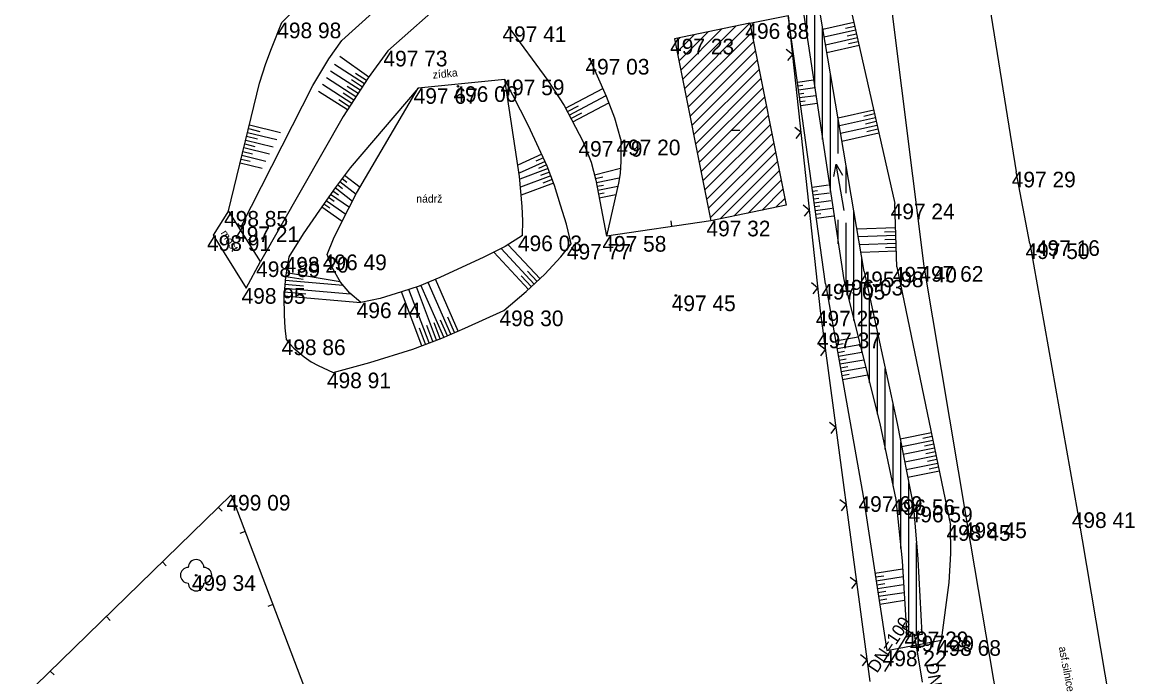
# Model space of a CAD drawing. Extents: x -554123 to -553118, y -1076825 to -1073672.
# Drawn here: x -553501.5 to -553430.4, y -1076768 to -1076726.2 of the extents above; entities that cross this region are included whole.
import ezdxf

# ---------------------------------------------------------------- set-up
doc = ezdxf.new("R2010")
doc.units = 0
for name, color, linetype in [('1', 7, 'Continuous'), ('12', 7, 'Continuous'), ('14', 7, 'Continuous'), ('17', 7, 'Continuous'), ('18', 7, 'Continuous'), ('26', 7, 'Continuous'), ('27', 7, 'Continuous'), ('28', 7, 'Continuous'), ('32', 7, 'Continuous'), ('34', 7, 'Continuous'), ('40', 7, 'Continuous'), ('47', 7, 'Continuous'), ('49', 7, 'Continuous'), ('52', 7, 'Continuous'), ('6', 7, 'Continuous')]:
    doc.layers.add(name, color=color, linetype=linetype)

# ---------------------------------------------------------------- blocks, each defined once
blk = doc.blocks.new('POINT_DISPLAY')
blk.add_line((0, 0), (0, 0))
blk = doc.blocks.new('T')
at = {"layer": '6'}
blk.add_circle((0, 0), 0.05, dxfattribs=at)
blk = doc.blocks.new('VOTOK')
at = {"layer": '28'}
for p, q in [((-3.001, 0), (0, 0)), ((-0.75, 0.282), (0, 0)), ((0, 0), (-0.75, -0.28))]:
    blk.add_line(p, q, dxfattribs=at)
blk = doc.blocks.new('JS800')
at = {"layer": '49'}
blk.add_text('DN=800', height=0.8, rotation=359.99988, dxfattribs=at).set_placement((0, 0))
blk = doc.blocks.new('STL')
at = {"layer": '34'}
blk.add_circle((0, 0), 0.05, dxfattribs=at)
for centre, start, end in [((0, 0.5), 0, 180), ((-0.5, 0), 90, 270), ((0.5, 0), 270, 90), ((0, -0.5), 180, 0)]:
    blk.add_arc(centre, 0.5, start, end, dxfattribs=at)
blk = doc.blocks.new('VYUST')
at = {"layer": '40'}
for p, q in [((-0.35, 0.501), (0, 0.5)), ((0, 0.5), (0, -0.5)), ((0, 0), (3, 0)), ((-0.35, -0.5), (0, -0.5))]:
    blk.add_line(p, q, dxfattribs=at)
blk = doc.blocks.new('BN')
at = {"layer": '47'}
blk.add_line((-0.25, 0), (0.25, 0), dxfattribs=at)
blk = doc.blocks.new('JS100')
at = {"layer": '49'}
blk.add_text('DN=100', height=0.8, rotation=359.99998, dxfattribs=at).set_placement((0, 0))

msp = doc.modelspace()

# ---------------------------------------------------------------- linework, layer by layer
at = {"layer": '12'}
for p, q in [((-553455.03, -1076726.24), (-553452.578, -1076725.751)), ((-553452.578, -1076725.751), (-553450.54, -1076744.62)), ((-553452.31, -1076728.237), (-553452.7, -1076727.923)), ((-553452.31, -1076728.237), (-553452.623, -1076728.627)), ((-553451.773, -1076733.208), (-553452.163, -1076732.894)), ((-553451.773, -1076733.208), (-553452.087, -1076733.598)), ((-553451.236, -1076738.179), (-553451.626, -1076737.865)), ((-553451.236, -1076738.179), (-553451.55, -1076738.569)), ((-553457.53, -1076738.86), (-553464.18, -1076739.84)), ((-553460.003, -1076739.224), (-553460.054, -1076738.878)), ((-553450.699, -1076743.15), (-553451.089, -1076742.836)), ((-553450.699, -1076743.15), (-553451.013, -1076743.54)), ((-553450.54, -1076744.62), (-553447.37, -1076768.32)), ((-553450.209, -1076747.098), (-553450.606, -1076746.794)), ((-553450.209, -1076747.098), (-553450.513, -1076747.496)), ((-553449.546, -1076752.054), (-553449.943, -1076751.75)), ((-553449.546, -1076752.054), (-553449.85, -1076752.452)), ((-553501.52, -1076769.39), (-553488.17, -1076756.39)), ((-553488.17, -1076756.39), (-553482.04, -1076772.53)), ((-553488.982, -1076757.181), (-553488.738, -1076757.432)), ((-553448.883, -1076757.01), (-553449.281, -1076756.706)), ((-553448.883, -1076757.01), (-553449.187, -1076757.407)), ((-553487.282, -1076758.727), (-553487.61, -1076758.851)), ((-553492.565, -1076760.669), (-553492.32, -1076760.92)), ((-553448.22, -1076761.966), (-553448.618, -1076761.662)), ((-553448.22, -1076761.966), (-553448.524, -1076762.363)), ((-553485.507, -1076763.401), (-553485.834, -1076763.526)), ((-553496.147, -1076764.158), (-553495.903, -1076764.408)), ((-553447.557, -1076766.921), (-553447.955, -1076766.617)), ((-553447.557, -1076766.921), (-553447.861, -1076767.319)), ((-553499.729, -1076767.646), (-553499.485, -1076767.897))]:
    msp.add_line(p, q, dxfattribs=at)
at = {"layer": '14'}
for p, q in [((-553455.03, -1076726.24), (-553459.85, -1076727.23)), ((-553455.03, -1076726.24), (-553452.71, -1076737.87)), ((-553459.85, -1076727.23), (-553457.53, -1076738.86)), ((-553452.71, -1076737.87), (-553457.53, -1076738.86))]:
    msp.add_line(p, q, dxfattribs=at)
at = {"layer": '17'}
for p, q in [((-553440.39, -1076721), (-553438.01, -1076735.73)), ((-553446.23, -1076723.25), (-553443.91, -1076741.76)), ((-553437.14, -1076740.31), (-553438.01, -1076735.73)), ((-553437.14, -1076740.31), (-553434.09, -1076757.5)), ((-553443.91, -1076741.76), (-553441.16, -1076758.15)), ((-553434.09, -1076757.5), (-553431.22, -1076774.44)), ((-553441.16, -1076758.15), (-553438.18, -1076775.84))]:
    msp.add_line(p, q, dxfattribs=at)
at = {"layer": '18'}
for p, q in [((-553470.68, -1076729.84), (-553476.23, -1076730.39)), ((-553488.35, -1076738.24), (-553489.32, -1076739.79)), ((-553486.29, -1076741.46), (-553488.35, -1076738.24)), ((-553489.32, -1076739.79), (-553487.22, -1076743.17)), ((-553487.22, -1076743.17), (-553486.29, -1076741.46))]:
    msp.add_line(p, q, dxfattribs=at)
at = {"layer": '26'}
for p, q in [((-553448.377, -1076726.199), (-553450.355, -1076726.645)), ((-553448.322, -1076726.443), (-553448.919, -1076726.577)), ((-553448.267, -1076726.687), (-553450.271, -1076727.138)), ((-553448.157, -1076727.174), (-553450.187, -1076727.631)), ((-553448.212, -1076726.93), (-553448.817, -1076727.066)), ((-553448.047, -1076727.662), (-553450.103, -1076728.125)), ((-553448.102, -1076727.418), (-553448.715, -1076727.556)), ((-553479.378, -1076729.688), (-553481.223, -1076728.367)), ((-553479.924, -1076730.526), (-553481.822, -1076729.297)), ((-553479.652, -1076730.106), (-553481.567, -1076728.867)), ((-553479.516, -1076729.896), (-553480.216, -1076729.443)), ((-553480.467, -1076731.365), (-553482.333, -1076730.157)), ((-553480.196, -1076730.945), (-553482.077, -1076729.727)), ((-553479.788, -1076730.316), (-553480.486, -1076729.864)), ((-553451.986, -1076730.003), (-553450.952, -1076729.859)), ((-553451.951, -1076730.251), (-553451.64, -1076730.208)), ((-553480.739, -1076731.785), (-553482.582, -1076730.592)), ((-553480.331, -1076731.155), (-553481.019, -1076730.71)), ((-553480.06, -1076730.736), (-553480.753, -1076730.287)), ((-553466.806, -1076731.665), (-553464.418, -1076730.411)), ((-553466.573, -1076732.107), (-553464.214, -1076730.868)), ((-553451.917, -1076730.499), (-553450.877, -1076730.354)), ((-553451.882, -1076730.746), (-553451.57, -1076730.703)), ((-553451.848, -1076730.994), (-553450.803, -1076730.848)), ((-553480.603, -1076731.575), (-553481.286, -1076731.133)), ((-553466.69, -1076731.886), (-553465.978, -1076731.512)), ((-553466.341, -1076732.55), (-553464.031, -1076731.337)), ((-553451.813, -1076731.241), (-553451.499, -1076731.197)), ((-553451.779, -1076731.489), (-553450.729, -1076731.343)), ((-553466.457, -1076732.329), (-553465.756, -1076731.961)), ((-553447.116, -1076731.795), (-553449.394, -1076732.308)), ((-553447.006, -1076732.282), (-553449.31, -1076732.801)), ((-553447.061, -1076732.038), (-553447.749, -1076732.193)), ((-553487.064, -1076732.978), (-553486.342, -1076733.155)), ((-553487.005, -1076732.735), (-553485.023, -1076733.22)), ((-553446.896, -1076732.77), (-553449.226, -1076733.295)), ((-553446.951, -1076732.526), (-553447.646, -1076732.683)), ((-553446.842, -1076733.014), (-553447.544, -1076733.172)), ((-553487.242, -1076733.706), (-553485.489, -1076734.135)), ((-553487.183, -1076733.464), (-553486.495, -1076733.632)), ((-553487.124, -1076733.221), (-553485.256, -1076733.678)), ((-553446.787, -1076733.258), (-553449.142, -1076733.789)), ((-553487.42, -1076734.435), (-553486.8, -1076734.586)), ((-553487.361, -1076734.192), (-553485.723, -1076734.593)), ((-553487.302, -1076733.949), (-553486.648, -1076734.109)), ((-553487.598, -1076735.164), (-553486.189, -1076735.509)), ((-553487.539, -1076734.921), (-553486.954, -1076735.064)), ((-553487.48, -1076734.678), (-553485.956, -1076735.051)), ((-553468.326, -1076734.614), (-553469.856, -1076735.317)), ((-553468.117, -1076735.068), (-553469.779, -1076735.832)), ((-553468.221, -1076734.841), (-553468.7, -1076735.061)), ((-553467.92, -1076735.527), (-553469.734, -1076736.199)), ((-553468.013, -1076735.295), (-553468.532, -1076735.534)), ((-553467.833, -1076735.762), (-553468.397, -1076735.971)), ((-553464.951, -1076735.926), (-553463.303, -1076735.503)), ((-553481.382, -1076736.55), (-553481.057, -1076736.801)), ((-553481.229, -1076736.352), (-553480.181, -1076737.16)), ((-553481.076, -1076736.154), (-553480.771, -1076736.39)), ((-553480.924, -1076735.956), (-553479.93, -1076736.723)), ((-553467.746, -1076735.996), (-553469.689, -1076736.716)), ((-553467.573, -1076736.465), (-553469.645, -1076737.233)), ((-553467.66, -1076736.23), (-553468.262, -1076736.454)), ((-553464.889, -1076736.168), (-553464.418, -1076736.047)), ((-553464.836, -1076736.412), (-553463.369, -1076736.131)), ((-553464.789, -1076736.658), (-553464.375, -1076736.579)), ((-553451.051, -1076736.72), (-553450.01, -1076736.575)), ((-553481.819, -1076737.159), (-553480.613, -1076737.992)), ((-553481.677, -1076736.954), (-553481.323, -1076737.198)), ((-553481.534, -1076736.748), (-553480.415, -1076737.611)), ((-553464.742, -1076736.903), (-553463.462, -1076736.658)), ((-553464.695, -1076737.149), (-553464.343, -1076737.082)), ((-553464.648, -1076737.394), (-553463.582, -1076737.19)), ((-553451.016, -1076736.968), (-553450.702, -1076736.924)), ((-553450.982, -1076737.215), (-553449.931, -1076737.069)), ((-553482.387, -1076737.982), (-553481.077, -1076738.886)), ((-553482.245, -1076737.776), (-553481.86, -1076738.042)), ((-553482.103, -1076737.571), (-553480.845, -1076738.439)), ((-553481.961, -1076737.365), (-553481.591, -1076737.62)), ((-553450.947, -1076737.463), (-553450.63, -1076737.419)), ((-553450.913, -1076737.711), (-553449.851, -1076737.563)), ((-553450.878, -1076737.958), (-553450.558, -1076737.913)), ((-553450.844, -1076738.206), (-553449.771, -1076738.057)), ((-553450.809, -1076738.453), (-553450.486, -1076738.408)), ((-553450.775, -1076738.701), (-553449.691, -1076738.55)), ((-553445.716, -1076739.315), (-553448.165, -1076739.4)), ((-553445.699, -1076739.815), (-553448.085, -1076739.898)), ((-553445.708, -1076739.565), (-553446.433, -1076739.59)), ((-553445.69, -1076740.064), (-553446.397, -1076740.089)), ((-553469.166, -1076743.25), (-553471.385, -1076740.872)), ((-553468.8, -1076742.909), (-553470.914, -1076740.644)), ((-553468.435, -1076742.568), (-553470.464, -1076740.394)), ((-553445.682, -1076740.314), (-553448.006, -1076740.394)), ((-553445.665, -1076740.814), (-553447.926, -1076740.892)), ((-553445.673, -1076740.564), (-553446.361, -1076740.588)), ((-553484.645, -1076742.175), (-553481.205, -1076742.744)), ((-553468.618, -1076742.738), (-553469.236, -1076742.076)), ((-553484.732, -1076742.919), (-553483.548, -1076743.02)), ((-553484.711, -1076742.67), (-553481.012, -1076742.986)), ((-553484.685, -1076742.421), (-553483.571, -1076742.605)), ((-553474.587, -1076746.314), (-553476.042, -1076742.991)), ((-553474.129, -1076746.114), (-553475.58, -1076742.8)), ((-553473.671, -1076745.913), (-553475.118, -1076742.608)), ((-553468.983, -1076743.08), (-553469.633, -1076742.383)), ((-553484.796, -1076743.666), (-553479.896, -1076744.084)), ((-553484.775, -1076743.417), (-553483.408, -1076743.534)), ((-553484.754, -1076743.168), (-553480.54, -1076743.528)), ((-553475.988, -1076746.849), (-553477.284, -1076743.405)), ((-553475.52, -1076746.673), (-553476.808, -1076743.25)), ((-553475.052, -1076746.497), (-553476.332, -1076743.096)), ((-553473.9, -1076746.013), (-553474.335, -1076745.021)), ((-553475.754, -1076746.761), (-553476.142, -1076745.731)), ((-553475.286, -1076746.585), (-553475.671, -1076745.561)), ((-553474.818, -1076746.409), (-553475.201, -1076745.39)), ((-553474.358, -1076746.214), (-553474.794, -1076745.218)), ((-553449.547, -1076746.538), (-553448.116, -1076746.285)), ((-553449.503, -1076746.784), (-553449.069, -1076746.707)), ((-553449.459, -1076747.031), (-553447.994, -1076746.772)), ((-553449.416, -1076747.277), (-553448.971, -1076747.198)), ((-553449.372, -1076747.523), (-553447.872, -1076747.258)), ((-553449.329, -1076747.769), (-553448.873, -1076747.688)), ((-553449.285, -1076748.015), (-553447.75, -1076747.743)), ((-553449.242, -1076748.261), (-553448.776, -1076748.179)), ((-553449.198, -1076748.508), (-553447.628, -1076748.23)), ((-553449.155, -1076748.754), (-553448.678, -1076748.67)), ((-553449.111, -1076749), (-553447.506, -1076748.716)), ((-553443.427, -1076752.413), (-553445.416, -1076752.826)), ((-553443.325, -1076752.903), (-553445.32, -1076753.318)), ((-553443.376, -1076752.658), (-553443.974, -1076752.782)), ((-553443.224, -1076753.392), (-553445.225, -1076753.808)), ((-553443.275, -1076753.148), (-553443.874, -1076753.272)), ((-553443.173, -1076753.637), (-553443.774, -1076753.762)), ((-553443.122, -1076753.882), (-553445.13, -1076754.299)), ((-553443.02, -1076754.371), (-553445.035, -1076754.79)), ((-553443.071, -1076754.127), (-553443.675, -1076754.252)), ((-553442.919, -1076754.861), (-553444.94, -1076755.281)), ((-553442.969, -1076754.616), (-553443.575, -1076754.742)), ((-553447.033, -1076761.383), (-553445.265, -1076761.111)), ((-553446.995, -1076761.63), (-553446.471, -1076761.55)), ((-553446.957, -1076761.877), (-553445.233, -1076761.612)), ((-553446.919, -1076762.125), (-553446.409, -1076762.046)), ((-553446.881, -1076762.372), (-553445.201, -1076762.113)), ((-553446.843, -1076762.619), (-553446.346, -1076762.542)), ((-553446.805, -1076762.866), (-553445.17, -1076762.614)), ((-553446.767, -1076763.113), (-553446.283, -1076763.039)), ((-553446.729, -1076763.36), (-553445.138, -1076763.115))]:
    msp.add_line(p, q, dxfattribs=at)
at = {"layer": '27'}
for p, q in [((-553478.17, -1076728), (-553473.83, -1076724.16)), ((-553448.78, -1076724.41), (-553445.77, -1076737.77)), ((-553450.19, -1076742.9), (-553452.578, -1076725.751)), ((-553445.63, -1076741.81), (-553445.77, -1076737.77)), ((-553445.63, -1076741.81), (-553442.2, -1076758.32)), ((-553450.19, -1076742.9), (-553447.79, -1076756.47)), ((-553447.79, -1076756.47), (-553446.27, -1076766.34)), ((-553446.27, -1076766.34), (-553442.79, -1076765.67))]:
    msp.add_line(p, q, dxfattribs=at)
for points in [[(-553484.94, -1076726.2), (-553483.576, -1076724.851), (-553482.505, -1076723.954), (-553479.08, -1076721.06)], [(-553488.35, -1076738.24), (-553486.356, -1076730.078), (-553485.958, -1076728.811), (-553485.603, -1076727.849), (-553484.94, -1076726.2)], [(-553470.47, -1076726.44), (-553467.928, -1076729.9), (-553466.897, -1076731.491), (-553465.7, -1076733.77)], [(-553478.17, -1076728), (-553479.414, -1076729.738), (-553481.007, -1076732.199), (-553486.29, -1076741.46)], [(-553463.28, -1076733.68), (-553463.656, -1076732.316), (-553464.186, -1076730.932), (-553465.26, -1076728.52)], [(-553466.45, -1076740.34), (-553466.742, -1076739.092), (-553467.118, -1076737.87), (-553467.516, -1076736.618), (-553467.98, -1076735.366), (-553469.165, -1076732.788), (-553470.68, -1076729.84)], [(-553469.56, -1076739.81), (-553469.524, -1076738.87), (-553469.583, -1076737.957), (-553469.747, -1076736.043), (-553470.68, -1076729.84)], [(-553476.23, -1076730.39), (-553480.559, -1076735.483), (-553481.536, -1076736.75), (-553482.533, -1076738.194), (-553483.569, -1076739.696), (-553484.48, -1076741.18)], [(-553482.03, -1076741.02), (-553481.639, -1076740.02), (-553481.168, -1076739.062), (-553480.152, -1076737.103), (-553476.23, -1076730.39)], [(-553465.7, -1076733.77), (-553465.159, -1076735.115), (-553464.864, -1076736.264), (-553464.18, -1076739.84)], [(-553463.28, -1076733.68), (-553463.273, -1076735.056), (-553463.325, -1076735.837), (-553463.42, -1076736.47), (-553464.18, -1076739.84)], [(-553469.56, -1076739.81), (-553470.658, -1076740.52), (-553472.028, -1076741.183), (-553474.844, -1076742.495), (-553476.16, -1076743.04), (-553477.294, -1076743.408), (-553478.649, -1076743.835), (-553479.89, -1076744.09)], [(-553470.75, -1076744.6), (-553469.32, -1076743.394), (-553468.12, -1076742.274), (-553467.111, -1076741.169), (-553466.45, -1076740.34)], [(-553484.48, -1076741.18), (-553484.695, -1076742.48), (-553484.802, -1076743.733), (-553484.784, -1076744.896), (-553484.739, -1076745.713), (-553484.66, -1076746.45)], [(-553479.89, -1076744.09), (-553480.593, -1076743.482), (-553481.178, -1076742.79), (-553481.713, -1076741.861), (-553482.03, -1076741.02)], [(-553481.66, -1076748.57), (-553479.301, -1076747.931), (-553476.553, -1076747.062), (-553474.712, -1076746.369), (-553473.232, -1076745.721), (-553470.75, -1076744.6)], [(-553484.66, -1076746.45), (-553484.423, -1076746.73), (-553484.169, -1076747.002), (-553483.506, -1076747.563), (-553483.053, -1076747.871), (-553482.622, -1076748.122), (-553481.66, -1076748.57)], [(-553442.79, -1076765.67), (-553442.296, -1076761.98), (-553442.191, -1076760.133), (-553442.2, -1076758.32)]]:
    msp.add_lwpolyline(points, dxfattribs=at)
at = {"layer": '28'}
for p, q in [((-553481.106, -1076727.336), (-553468.69, -1076716.15)), ((-553451.877, -1076723.705), (-553449.03, -1076742.64)), ((-553447.73, -1076742.11), (-553450.902, -1076723.42))]:
    msp.add_line(p, q, dxfattribs=at)
for points in [[(-553487.54, -1076739.23), (-553482.947, -1076730.215), (-553481.933, -1076728.507), (-553481.106, -1076727.336)], [(-553447.73, -1076742.11), (-553445.611, -1076751.817), (-553444.58, -1076757.14)], [(-553449.03, -1076742.64), (-553446.728, -1076751.817), (-553445.7, -1076756.67)], [(-553445.7, -1076756.67), (-553445.297, -1076760.603), (-553444.991, -1076765.436)], [(-553444.58, -1076757.14), (-553444.285, -1076760.498), (-553444.032, -1076765.262)]]:
    msp.add_lwpolyline(points, dxfattribs=at)
at = {"layer": '32'}
for p, q in [((-553451.377, -1076727.03), (-553451.377, -1076723.559)), ((-553450.877, -1076730.356), (-553450.877, -1076723.567)), ((-553459.448, -1076729.244), (-553456.81, -1076726.606)), ((-553459.331, -1076729.834), (-553455.92, -1076726.423)), ((-553459.213, -1076730.423), (-553455.03, -1076726.24)), ((-553450.377, -1076733.681), (-553450.377, -1076726.513)), ((-553459.801, -1076727.475), (-553459.479, -1076727.154)), ((-553459.683, -1076728.065), (-553458.59, -1076726.971)), ((-553459.566, -1076728.655), (-553457.7, -1076726.788)), ((-553459.095, -1076731.013), (-553454.912, -1076726.83)), ((-553458.978, -1076731.602), (-553454.795, -1076727.419)), ((-553458.86, -1076732.192), (-553454.677, -1076728.009)), ((-553458.743, -1076732.781), (-553454.56, -1076728.598)), ((-553458.625, -1076733.371), (-553454.442, -1076729.188)), ((-553449.877, -1076737.007), (-553449.877, -1076729.459)), ((-553458.507, -1076733.96), (-553454.324, -1076729.777)), ((-553458.39, -1076734.55), (-553454.207, -1076730.367)), ((-553458.272, -1076735.139), (-553454.089, -1076730.956)), ((-553458.155, -1076735.729), (-553453.972, -1076731.546)), ((-553458.037, -1076736.318), (-553453.854, -1076732.135)), ((-553457.919, -1076736.908), (-553453.736, -1076732.725)), ((-553449.377, -1076734.57), (-553449.377, -1076732.406)), ((-553457.802, -1076737.497), (-553453.619, -1076733.314)), ((-553457.684, -1076738.087), (-553453.501, -1076733.904)), ((-553457.567, -1076738.676), (-553453.384, -1076734.493)), ((-553456.918, -1076738.734), (-553453.266, -1076735.083)), ((-553456.028, -1076738.551), (-553453.148, -1076735.672)), ((-553448.877, -1076737.091), (-553448.877, -1076735.352)), ((-553455.138, -1076738.369), (-553453.031, -1076736.262)), ((-553454.248, -1076738.186), (-553452.913, -1076736.851)), ((-553453.358, -1076738.003), (-553452.796, -1076737.441)), ((-553448.377, -1076745.243), (-553448.377, -1076738.298)), ((-553449.377, -1076740.332), (-553449.377, -1076738.8)), ((-553448.877, -1076743.25), (-553448.877, -1076739.006)), ((-553447.877, -1076747.236), (-553447.877, -1076741.244)), ((-553447.377, -1076749.23), (-553447.377, -1076743.727)), ((-553446.877, -1076751.223), (-553446.877, -1076746.018)), ((-553446.377, -1076753.474), (-553446.377, -1076748.308)), ((-553445.877, -1076755.834), (-553445.877, -1076750.598)), ((-553445.377, -1076759.822), (-553445.377, -1076753.025)), ((-553444.877, -1076765.415), (-553444.877, -1076755.607)), ((-553444.377, -1076765.325), (-553444.377, -1076759.451))]:
    msp.add_line(p, q, dxfattribs=at)

# ---------------------------------------------------------------- block references
at = {"layer": '1'}
for p in [(-553484.94, -1076726.2), (-553470.47, -1076726.44), (-553455.03, -1076726.24), (-553459.85, -1076727.23), (-553478.17, -1076728), (-553465.26, -1076728.52), (-553470.68, -1076729.84), (-553476.23, -1076730.39), (-553473.68, -1076730.27), (-553465.7, -1076733.77), (-553463.28, -1076733.68), (-553438.01, -1076735.73), (-553445.77, -1076737.77), (-553488.35, -1076738.24), (-553487.54, -1076739.23), (-553457.53, -1076738.86), (-553489.32, -1076739.79), (-553469.56, -1076739.81), (-553464.18, -1076739.84), (-553436.36, -1076740.11), (-553466.45, -1076740.34), (-553437.14, -1076740.31), (-553486.29, -1076741.46), (-553484.48, -1076741.18), (-553482.03, -1076741.02), (-553447.73, -1076742.11), (-553445.63, -1076741.81), (-553443.91, -1076741.76), (-553450.19, -1076742.9), (-553449.03, -1076742.64), (-553487.22, -1076743.17), (-553459.76, -1076743.64), (-553479.89, -1076744.09), (-553470.75, -1076744.6), (-553450.54, -1076744.62), (-553484.66, -1076746.45), (-553450.47, -1076746.01), (-553481.66, -1076748.57), (-553488.17, -1076756.39), (-553447.79, -1076756.47), (-553445.7, -1076756.67), (-553444.58, -1076757.14), (-553434.09, -1076757.5), (-553442.2, -1076758.32), (-553441.16, -1076758.15), (-553490.41, -1076761.52), (-553444.87, -1076765.12), (-553444.51, -1076765.39), (-553442.79, -1076765.67), (-553446.27, -1076766.34)]:
    msp.add_blockref('POINT_DISPLAY', p, dxfattribs=at)
at = {"layer": '28', "xscale": 1.0000004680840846, "yscale": 1.0000004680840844, "rotation": 99.55474033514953}
msp.add_blockref('VOTOK', (-553449.503, -1076735.25), dxfattribs=at)
at = {"layer": '32'}
msp.add_blockref('POINT_DISPLAY', (-553455.03, -1076726.24), dxfattribs=at)
at = {"layer": '34'}
msp.add_blockref('STL', (-553490.41, -1076761.52), dxfattribs=at)
at = {"layer": '40'}
for p, xscale, yscale, rotation in [((-553444.87, -1076765.12), 1.0000002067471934, 1.000000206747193, -121.33662987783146), ((-553444.51, -1076765.39), 1.000000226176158, 1.000000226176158, -80.38924721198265)]:
    msp.add_blockref('VYUST', p, dxfattribs=dict(at, xscale=xscale, yscale=yscale, rotation=rotation))
at = {"layer": '47'}
msp.add_blockref('BN', (-553455.92, -1076733.072), dxfattribs=at)
at = {"layer": '49'}
for name, p, xscale, yscale, rotation in [('JS100', (-553446.899, -1076767.82), 1.0000008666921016, 1.0000008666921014, 56.38104481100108), ('JS800', (-553443.788, -1076767.17), 0.9999985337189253, 0.9999985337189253, -80.2438855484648)]:
    msp.add_blockref(name, p, dxfattribs=dict(at, xscale=xscale, yscale=yscale, rotation=rotation))
at = {"layer": '6'}
for p in [(-553465.26, -1076728.52), (-553473.68, -1076730.27), (-553487.54, -1076739.23), (-553459.76, -1076743.64)]:
    msp.add_blockref('T', p, dxfattribs=at)

# ---------------------------------------------------------------- texts
at = {"layer": '52'}
for s, rotation, p in [('zídka', 5.65948, (-553475.27, -1076729.786)), ('most', 301.85276, (-553488.86, -1076739.645)), ('asf.silnice', 280.74882, (-553435.297, -1076766.121))]:
    msp.add_text(s, height=0.5, rotation=rotation, dxfattribs=at).set_placement(p)
msp.add_text('nádrž', height=0.5, dxfattribs=at).set_placement((-553476.344, -1076737.702))
at = {"layer": '6'}
for s, p in [('498 98 ', (-553485.226, -1076727.2)), ('497 41 ', (-553470.837, -1076727.44)), ('496 88 ', (-553455.316, -1076727.24)), ('497 23 ', (-553460.122, -1076728.23)), ('497 73 ', (-553478.44, -1076729)), ('497 03 ', (-553465.534, -1076729.52)), ('497 59 ', (-553470.964, -1076730.84)), ('497 67 ', (-553476.512, -1076731.39)), ('496 00 ', (-553473.97, -1076731.27)), ('497 79 ', (-553465.982, -1076734.77)), ('497 20 ', (-553463.554, -1076734.68)), ('497 29 ', (-553438.294, -1076736.73)), ('497 24 ', (-553446.03, -1076738.77)), ('498 85 ', (-553488.624, -1076739.24)), ('497 21 ', (-553487.919, -1076740.23)), ('497 32 ', (-553457.802, -1076739.86)), ('498 91 ', (-553489.713, -1076740.79)), ('496 03 ', (-553469.848, -1076740.81)), ('497 58 ', (-553464.452, -1076740.84)), ('497 16 ', (-553436.753, -1076741.11)), ('497 77 ', (-553466.718, -1076741.34)), ('497 50 ', (-553437.414, -1076741.31)), ('498 89 ', (-553486.576, -1076742.46)), ('498 20 ', (-553484.756, -1076742.18)), ('496 49 ', (-553482.316, -1076742.02)), ('495 98 ', (-553448.016, -1076743.11)), ('497 40 ', (-553445.892, -1076742.81)), ('497 62 ', (-553444.194, -1076742.76)), ('497 05 ', (-553450.464, -1076743.9)), ('496 03 ', (-553449.318, -1076743.64)), ('498 95 ', (-553487.506, -1076744.17)), ('497 45 ', (-553460.02, -1076744.64)), ('496 44 ', (-553480.152, -1076745.09)), ('498 30 ', (-553471.026, -1076745.6)), ('497 25 ', (-553450.812, -1076745.62)), ('498 86 ', (-553484.946, -1076747.45)), ('497 37 ', (-553450.74, -1076747.01)), ('498 91 ', (-553482.053, -1076749.57)), ('499 09 ', (-553488.47, -1076757.39)), ('497 69 ', (-553448.086, -1076757.47)), ('496 56 ', (-553445.998, -1076757.67)), ('496 59 ', (-553444.878, -1076758.14)), ('498 41 ', (-553434.459, -1076758.5)), ('498 45 ', (-553442.462, -1076759.32)), ('498 45 ', (-553441.422, -1076759.15)), ('499 34 ', (-553490.684, -1076762.52)), ('497 29 ', (-553445.154, -1076766.12)), ('497 29 ', (-553444.794, -1076766.39)), ('498 68 ', (-553443.076, -1076766.67)), ('498 22 ', (-553446.544, -1076767.34))]:
    msp.add_text(s, height=1, dxfattribs=at).set_placement(p)

doc.saveas('drawing.dxf')
